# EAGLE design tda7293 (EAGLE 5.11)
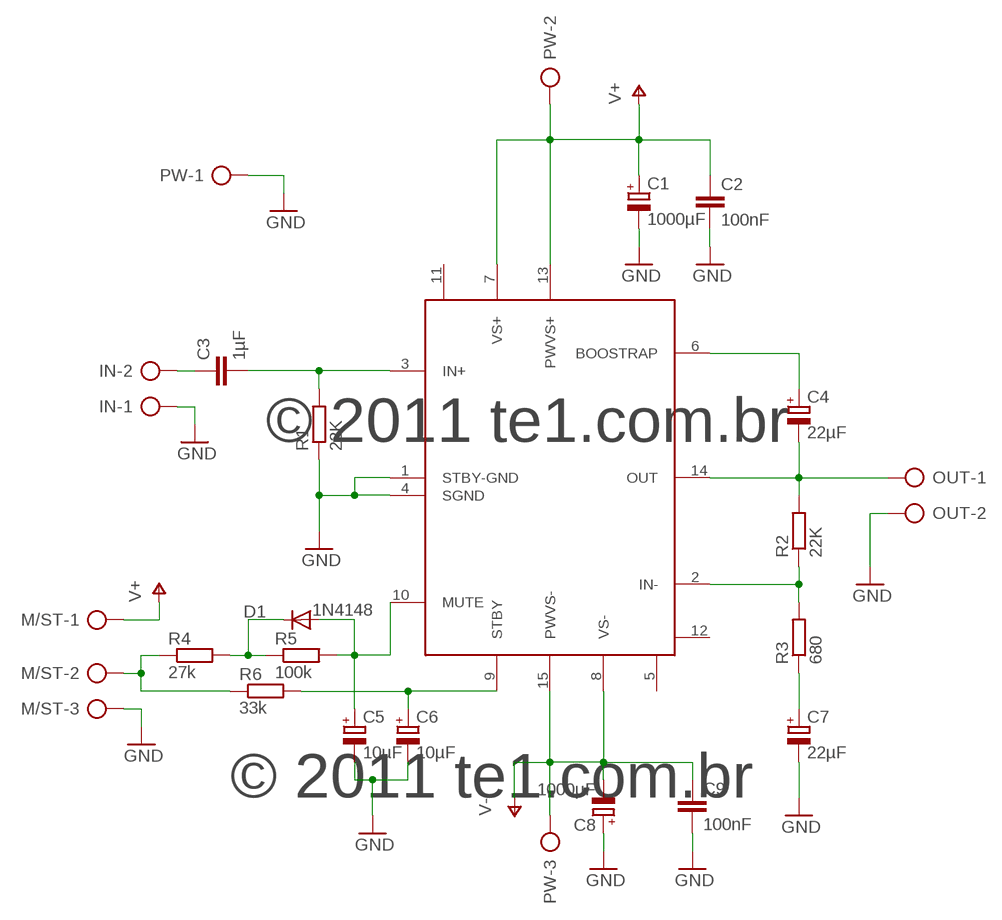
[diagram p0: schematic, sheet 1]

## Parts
C1  1000µF  CPOL-EUE5-10.5  [E5-10,5]
C2  100nF  C5/2.5  [C5B2.5]
C3  1µF  C15/6  [C15B6]
C4  22µF  CPOL-EUE2.5-6  [E2,5-6]
C5  10µF  CPOL-EUE1.8-4  [E1,8-4]
C6  10µF  CPOL-EUE1.8-4  [E1,8-4]
C7  22µF  CPOL-EUE2.5-6  [E2,5-6]
C8  1000µF  CPOL-EUE5-10.5  [E5-10,5]
C9  100nF  C5/2.5  [C5B2.5]
D1  1N4148  1N4148DO35-10  [DO35-10]
IC1  TDA7293V  [MULTIWATT15V]
IN  AK300/2  [AK300/2]
M/ST  AK300/3  [AK300/3]
OUT  AK300/2  [AK300/2]
PW  AK300/3  [AK300/3]
R1  22K  R-EU_0207/10  [0207/10]
R2  22K  R-EU_0207/10  [0207/10]
R3  680  R-EU_0207/10  [0207/10]
R4  27k  R-EU_0207/10  [0207/10]
R5  100k  R-EU_0207/10  [0207/10]
R6  33k  R-EU_0207/15  [0207/15]

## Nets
GND: C1.- C2.2 C5.- C6.- C7.- C8.+ C9.2 IC1.1(STBY-GND) IC1.4(SGND) IN.1 M/ST.3 OUT.2 PW.1 R1.1
N$1: C3.2 IC1.3(IN+) R1.2
N$2: C3.1 IN.2
N$3: C4.+ IC1.6(BOOSTRAP)
N$4: C4.- IC1.14(OUT) OUT.1 R2.2
N$5: IC1.2(IN-) R2.1 R3.2
N$6: C7.+ R3.1
N$9: D1.C R4.2 R5.1
N$10: M/ST.2 R4.1 R6.1
N$11: C5.+ D1.A IC1.10(MUTE) R5.2
N$12: C6.+ IC1.9(STBY) R6.2
V+: C1.+ C2.1 IC1.7(VS+) IC1.13(PWVS+) M/ST.1 PW.2
V-: C8.- C9.1 IC1.8(VS-) IC1.15(PWVS-) PW.3
Unconnected: IC1.5(CLIP) IC1.11(BUFFER) IC1.12(BOOTLOADER)

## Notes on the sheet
- © 2011 te1.com.br
- © 2011 te1.com.br

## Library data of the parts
C1 C4-C8 = rcl:CPOL-EU: POLARIZED CAPACITOR, European symbol
C2 C3 C9 = capacitor-wima:C: CAPACITOR
D1 = diode:1N4148: DIODE
IC1 = tda7293:TDA7293*: 120V - 100W DMOS Audio Amplifier with Mute/Standby
IN OUT = con-ptr500:AK300/2: CONNECTOR; OC_FARNELL: unknown; OC_NEWARK: unknown
M/ST PW = con-ptr500:AK300/3: CONNECTOR; OC_FARNELL: unknown; OC_NEWARK: unknown
R1-R6 = rcl:R-EU_: RESISTOR, European symbol

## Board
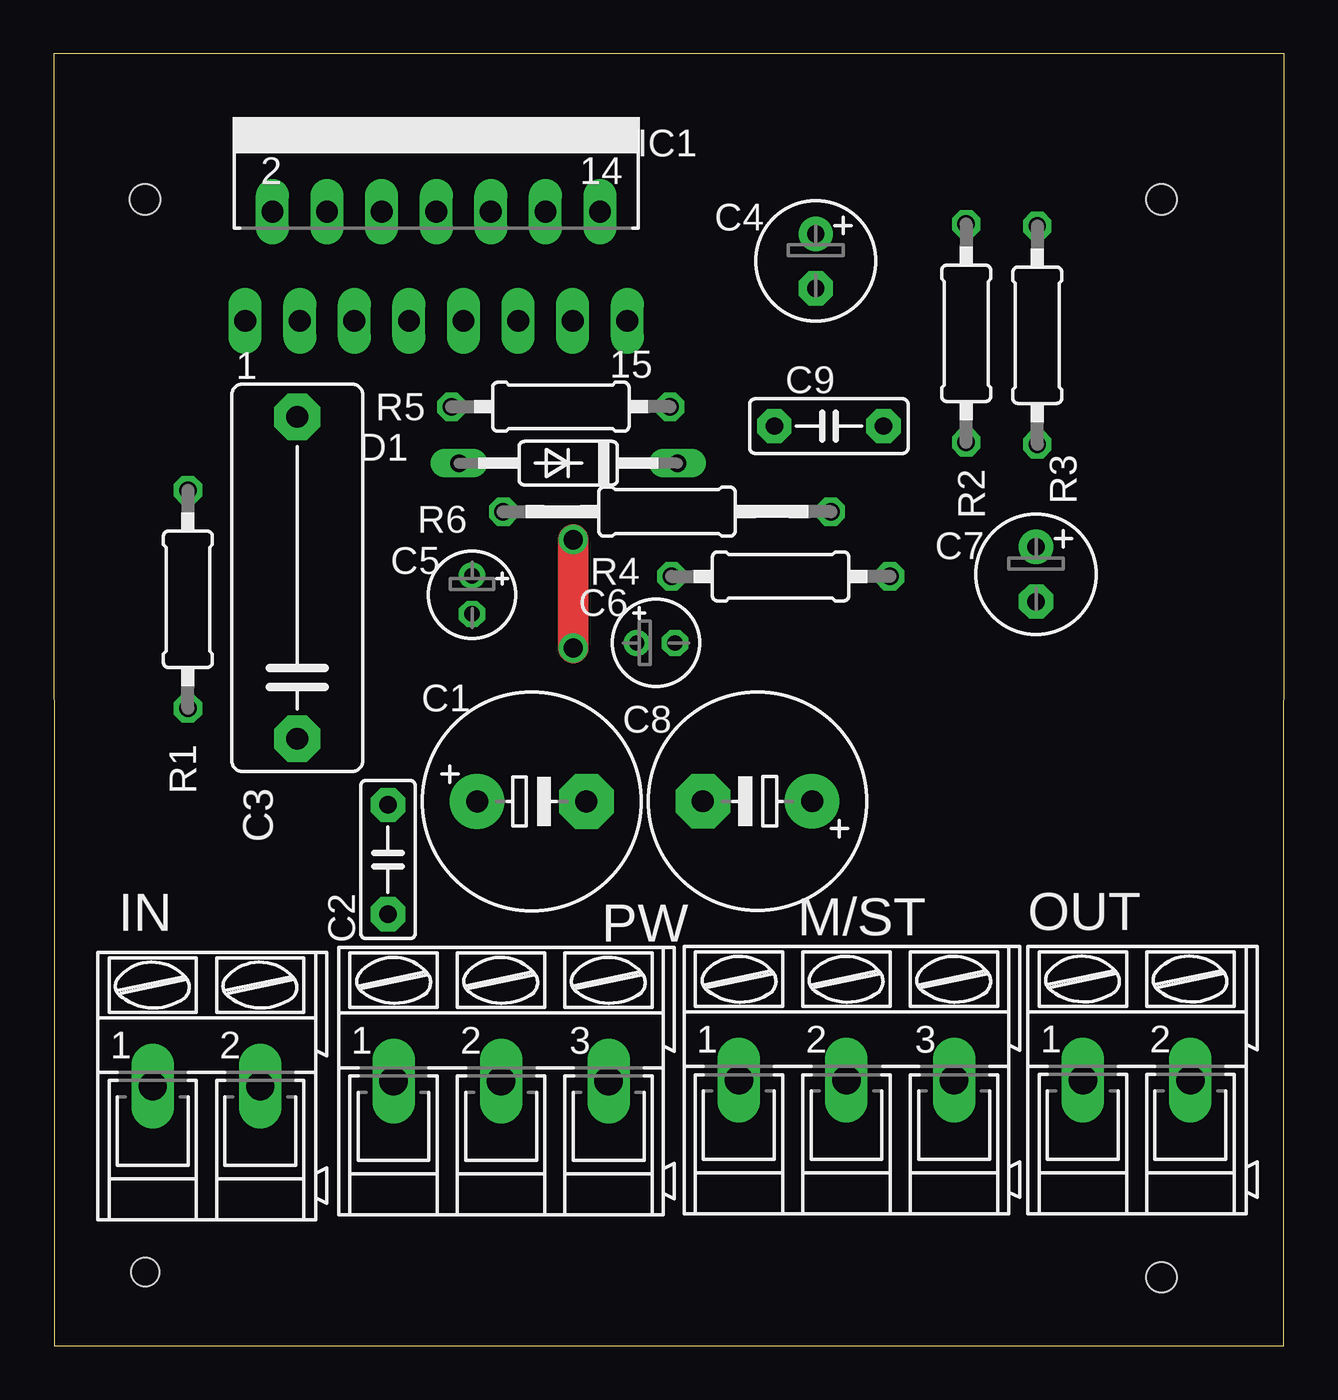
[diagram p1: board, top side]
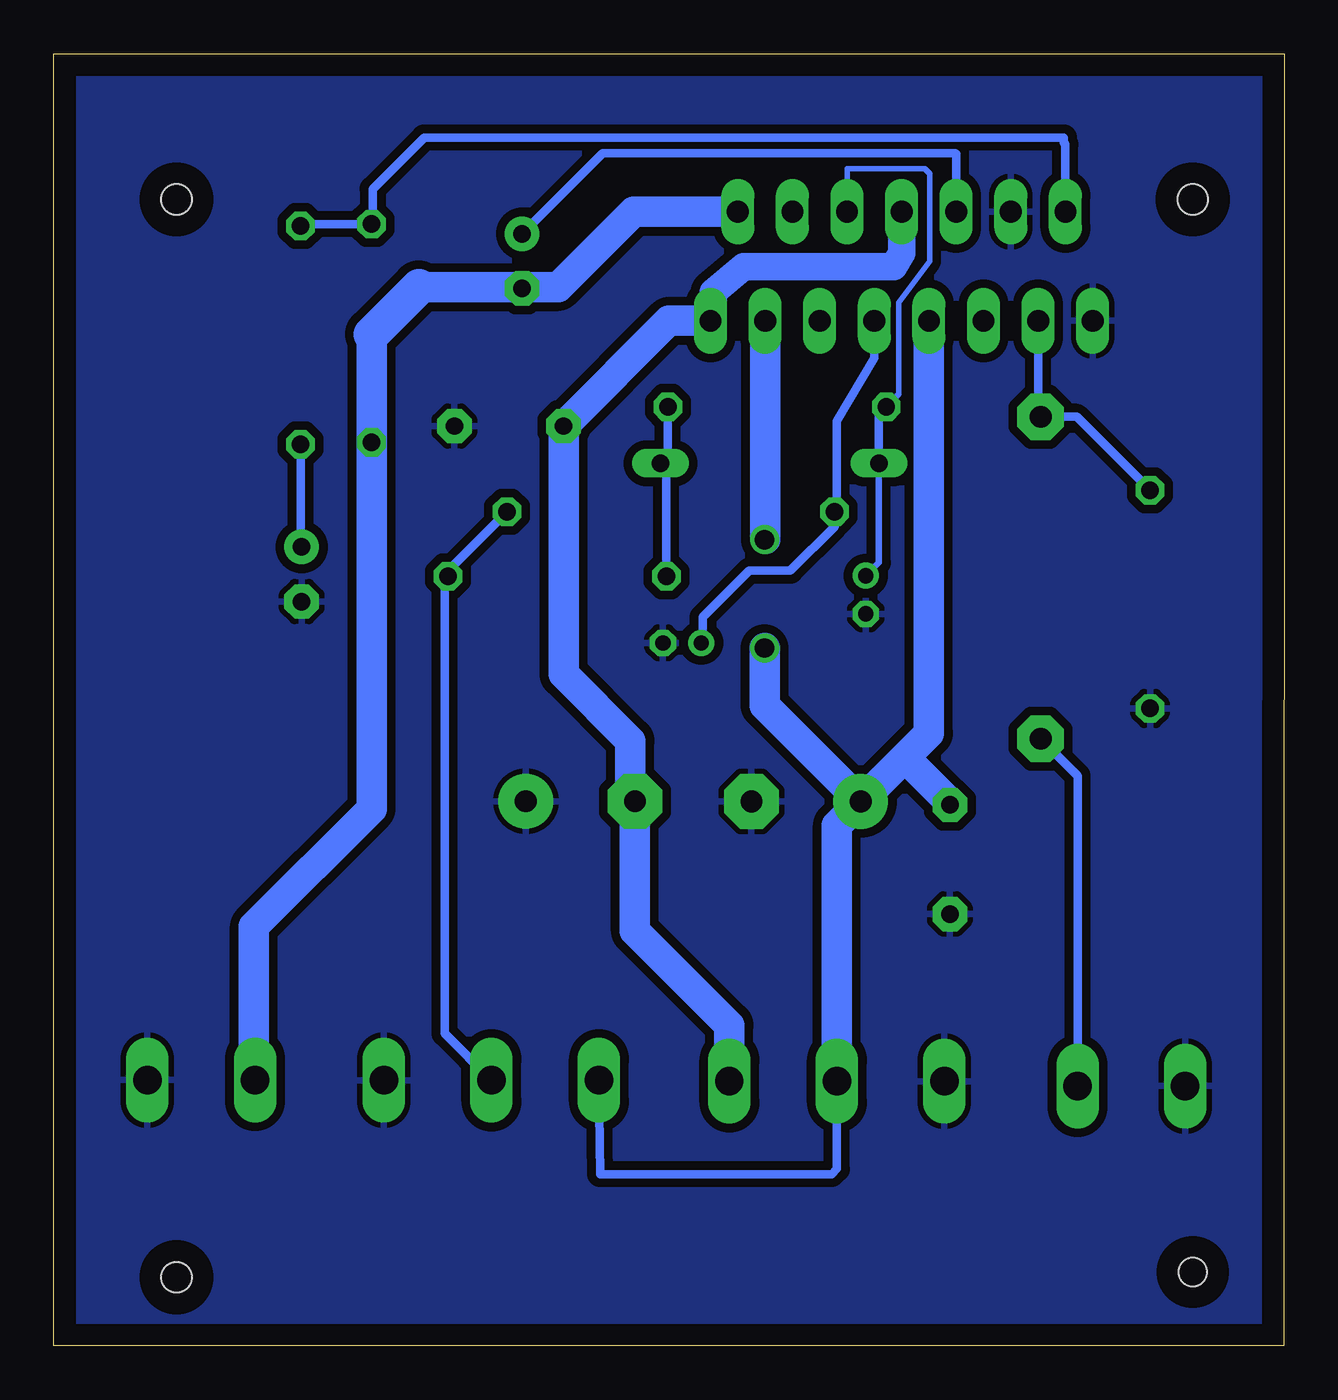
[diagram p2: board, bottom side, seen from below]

Size 57.24 x 60.13 mm. Coordinates in mm from the lower left corner, seen from the top.
Outline: 0.02,0 57.23,0 57.24,60.13 0,60.13 0.02,0
Copper layers (1*16): Top 0.035mm / dielectric 1.5mm / Bottom 0.035mm
Design rules "default": minimum track width 10mil, minimum drill 24mil, track to track 8mil, track to pad 8mil, pad to pad 8mil, via to via 8mil, smd to smd 8mil, copper to edge 40mil, drill to drill 8mil, minimum pad ring 10mil, minimum via ring 8mil, stop-mask expansion 4mil, vias tented up to drill 0mil, thermal gap 10mil
Holes 1.4 mm at 4.25,53.35 51.53,53.35 51.53,3.19
Holes 1.3 mm at 4.25,3.43

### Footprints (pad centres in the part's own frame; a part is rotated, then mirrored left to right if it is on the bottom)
E5-10,5 = drill 1.016 pad 2.54 round: + -2.54,0 | drill 1.016 pad 2.54 octagon: - 2.54,0
C5B2.5 = drill 0.813 pad 1.6 octagon: 1 -2.54,0; 2 2.54,0
C15B6 = drill 1.016 pad 2.159 octagon: 1 -7.493,0; 2 7.493,0
E2,5-6 = drill 0.813 pad 1.6 round: + -1.27,0 | drill 0.813 pad 1.6 octagon: - 1.27,0
E1,8-4 = drill 0.711 pad 1.168 round: + -0.889,0 | drill 0.711 pad 1.168 octagon: - 0.889,0
DO35-10 = drill 0.813 long: A 5.08,0; C -5.08,0
MULTIWATT15V = drill 1.016 long: 1 -8.89,-7.62; 2 -7.62,-2.54; 3 -6.35,-7.62; 4 -5.08,-2.54; 5 -3.81,-7.62; 6 -2.54,-2.54; 7 -1.27,-7.62; 8 0,-2.54; 9 1.27,-7.62; 10 2.54,-2.54; 11 3.81,-7.62; 12 5.08,-2.54; 13 6.35,-7.62; 14 7.62,-2.54; 15 8.89,-7.62
AK300/2 = drill 1.321 long: 1 -2.515,0; 2 2.489,0
AK300/3 = drill 1.321 long: 1 -5.004,0; 2 0,0; 3 5.004,0
0207/10 = drill 0.813 octagon: 1 -5.08,0; 2 5.08,0
0207/15 = drill 0.813 octagon: 1 -7.62,0; 2 7.62,0

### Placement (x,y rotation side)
C1  22.24,25.33 0 top
C2  15.55,22.63 270 top
C3  11.33,35.74 90 top
C4  35.45,50.48 270 top
C5  19.46,34.95 270 top
C6  28.01,32.71 0 top
C7  45.7,35.91 270 top
C8  32.74,25.34 180 top
C9  36.06,42.8 0 top
D1  23.93,41.08 180 top
IC1  17.79,55.32 0 top
IN  7.12,12.09 0 top
M/ST  36.88,12.36 0 top
OUT  50.39,12.37 0 top
PW  20.81,12.31 0 top
R1  6.24,34.74 90 top
R2  42.45,47.12 270 top
R3  45.75,47.03 90 top
R4  33.81,35.8 180 top
R5  23.59,43.7 180 top
R6  28.53,38.82 180 top

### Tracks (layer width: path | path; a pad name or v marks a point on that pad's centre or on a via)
GND
  pour Bottom (isolate 0.406): 0.89,59.35 0.89,0.55 56.33,0.55 56.33,59.35
N$1
  Bottom 0.406: IC1.3 11.44,43.35 C3.2 9.65,43.23 R1.2
N$2
  Bottom 0.406: IN.2 9.61,26.53 C3.1
N$3
  Bottom 0.406: IC1.6 15.25,55.47 15.29,55.51 31.69,55.51 C4.+
N$4
  Bottom 1.27: 35.51,49.27 C4.- 35.39,49.27
  Bottom 1.422: 42.45,47.07 R2.2 42.45,24.99 47.93,19.51 47.93,12.43 OUT.1 | 40.25,49.27 35.51,49.27 | IC1.14 30.26,52.78 33.77,49.27 35.39,49.27
  Bottom 1.676: 42.45,47.07 40.25,49.27
N$5
  Bottom 0.406: IC1.2 10.18,55.91 10.25,55.99 10.25,56.23 40.01,56.23 42.41,53.83 42.41,52.24 R2.1 45.42,52.2 R3.2
N$6
  Bottom 0.406: R3.1 45.75,37.22 C7.+
N$9
  Bottom 0.406: R4.2 28.73,40.8 D1.C 28.67,41.42 R5.1
N$10
  Bottom 0.406: R6.1 38.89,36.08 R4.1 39.05,35.8 39.05,14.53 M/ST.2
N$11
  Bottom 0.254: IC1.10 20.33,54.78 20.33,54.79 16.73,54.79 16.49,54.55 16.49,50.47 17.93,48.55 17.93,44.28 R5.2
  Bottom 0.305: D1.A 18.86,36.44 C5.+
  Bottom 0.406: D1.A 18.86,43.36 R5.2
N$12
  Bottom 0.406: C6.+ 27.05,32.78 27.05,33.91 24.89,36.07 22.97,36.07 20.91,38.13 R6.2 20.81,38.92 20.81,43.03 19.07,45.97 IC1.9
V+  (via drill 0.9)
  Top 1.422: v24.17,32.47 v24.17,37.51
  Bottom 0.406: PW.2 20.81,8.23 21.05,7.99 31.83,7.99 M/ST.1
  Bottom 1.27: v24.17,37.51 24.14,37.53 | 15.55,25.29 C2.1
  Bottom 1.422: 24.14,37.53 IC1.13 | v24.17,32.47 24.17,29.8 C1.+ | PW.2 20.81,24.22 C1.+ | IC1.7 16.52,28.5 17.64,27.39 | C1.+ 17.64,27.39 | 17.64,27.39 15.55,25.29
V-
  Bottom 1.27: IC1.8 17.79,50.84 18.17,50.23 25.13,50.23 26.57,49.03 26.57,47.81 IC1.15 | C8.- 30.41,25.55
  Bottom 1.422: IC1.15 28.62,47.7 C9.1 33.52,31.26 30.41,28.15 30.41,25.55 | C8.- 30.2,19.3 25.81,14.91 PW.3

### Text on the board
Holes: © 2011 te1.com.br | © 2011 te1.com.br | - | - | + | + | Mute/ST-by | OUT | IN | GND | +V | -V | © 2011 te1.com.br | POWER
